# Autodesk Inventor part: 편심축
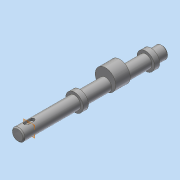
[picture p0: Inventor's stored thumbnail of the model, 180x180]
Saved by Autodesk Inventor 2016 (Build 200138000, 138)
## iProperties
Created: 2016-02
Part Number: 편심축
Material: 강철, 연강
Document SubType Name: Modeling
Designer: mduedu
Density: 1 g/cm^3
Appearance: 강철
Author: mduedu
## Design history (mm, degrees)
sketch "스케치1"
  geometry: C1 r 6 at (0, 0); 1 further point
  constraints: 1 centre point, 1 coincident
  dimensions: "d0" = 12 diameter of C1
extrude "돌출1" new body sketch "스케치1" distance "d1" = 140; taper "d2" = 0 deg
chamfer "모따기1" distance "d3" = 1; stored, may be unused: second distance "d4" = 2, angle "d5" = 45 deg
node "작업 평면1"
sketch "스케치2"
  geometry: C1 r 10 at (0, 4); C2 r 6 at (0, 0) reference; 1 further point
  constraints: 1 centre point, 1 tangent, 1 vertical alignment
  dimensions: "d7" = 20 diameter of C1
extrude "돌출2" join sketch "스케치2" stored distance "d8" = 14; taper "d9" = 0 deg
node "작업 평면2"
sketch "스케치3"
  geometry: C1 r 8.5 at (0, 0); 1 further point
  constraints: 1 centre point, 1 coincident
  dimensions: "d12" = 17 diameter of C1
extrude "돌출3" join sketch "스케치3" distance "d13" = 5; taper "d14" = 0 deg
node "작업 평면3"
sketch "스케치4"
  geometry: L1 (-5, 140)-(5, 140) reference; L2 (0, 140)-(0, 0); L3 (-2, 132)-(-2, 126); L4 (2, 126)-(2, 132); A1 r 2 centre (0, 132) between (2, 132) and (-2, 132); A2 r 2 centre (0, 126) between (-2, 126) and (2, 126)
  constraints: 6 end point, 4 point on circle, 4 tangent, 2 centre point, 2 point on line, 1 midpoint, 1 parallel, 1 perpendicular
  dimensions: "d15" = 4 distance between parallel lines of L3 L4; "d17" = 6 distance edge to line of A1 L1; "d18" = 10 dimension on A2 A1
extrude "돌출4" cut sketch "스케치4" distance "d19" = 2.5; taper "d20" = 0 deg
sketch "스케치5"
  geometry: L1 (6, 55)-(6, 139) reference; L2 (-6, 55)-(-6, 139) reference; L3 (6, 115)-(-6, 115); L4 (-5, 140)-(5, 140) reference; L5 (6, 116.5)-(4.5, 115); L6 (6, 116.5)-(6, 115); L7 (4.5, 115)-(6, 115); 1 further point
  constraints: 8 end point, 4 point on line, 2 collinear, 1 perpendicular
  dimensions: "d21" = 25 distance between parallel lines of L3 L4; "d22" = 3 diameter of L5.start L3; "d24" = 45 deg angle of L3 L5
revolve "회전1" sketch "스케치5" stored, may be unused: angle "d25" = 90 deg
sketch "스케치6"
  geometry: L1 (6, 116.5)-(4.5, 115) reference; L2 (6, 113.5)-(4.5, 115) reference; 2 further points
  constraints: 1 coincident
node "작업 평면4"
sketch "스케치7"
  geometry: C1 r 8.5 at (0, -4); 1 further point
  constraints: 1 centre point, 1 coincident
  dimensions: "d27" = 17 diameter of C1
extrude "돌출5" join sketch "스케치7" distance "d29" = 5; taper "d30" = 0 deg
node "작업 평면5"
node "솔리드1"
other parameters: "d6" = -48, "d11" = -11, "d31" = -11
